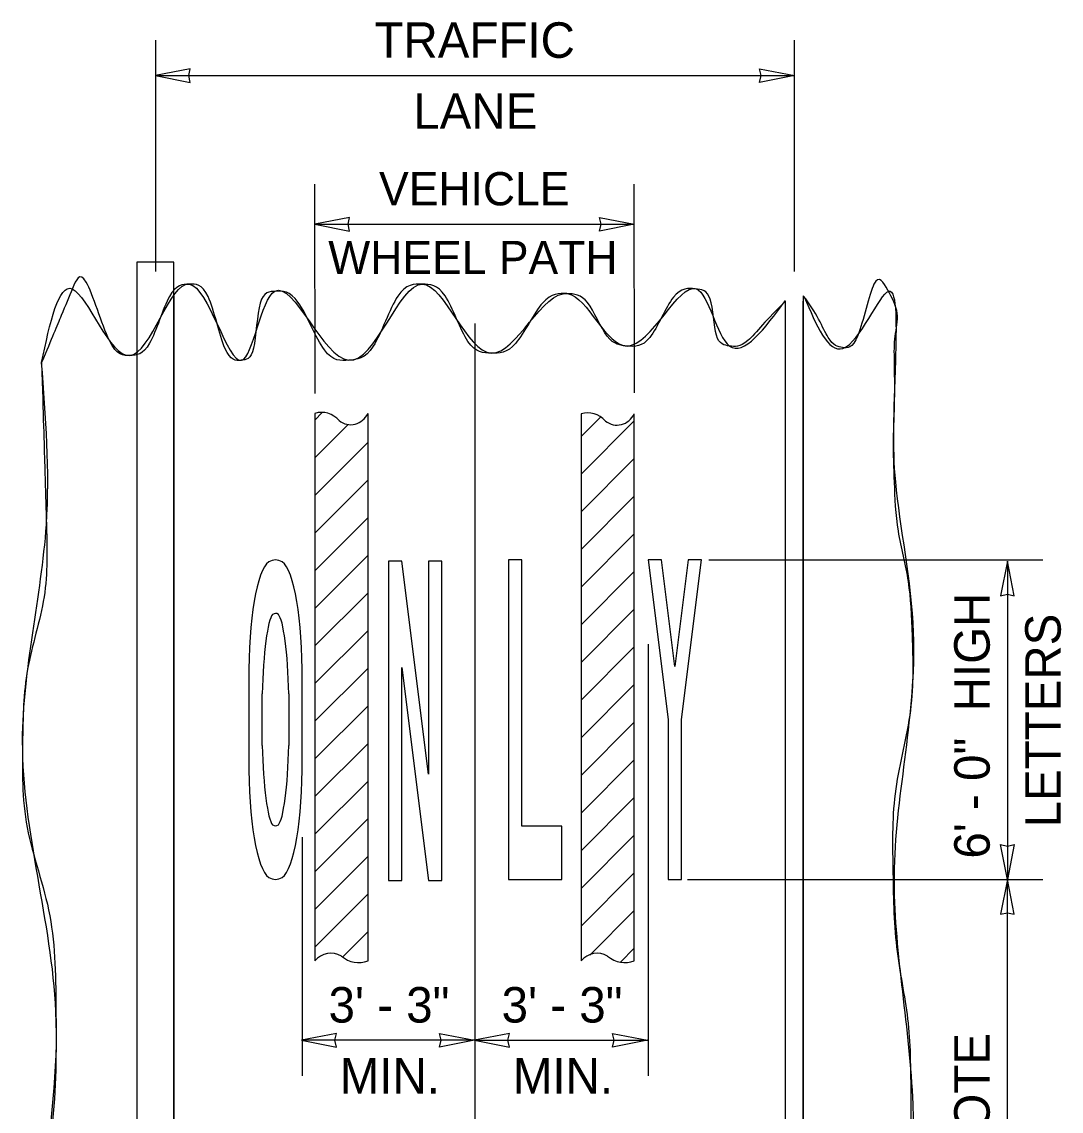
# Model space of a CAD drawing. Extents: x 99862 to 103151, y 100000 to 105076.
# Drawn here: x 100952.5 to 101421, y 103470.7 to 103961.7 of the extents above; entities that cross this region are included whole.
import ezdxf

# ---------------------------------------------------------------- set-up
doc = ezdxf.new("R2010")
doc.units = 0
for name, color, linetype in [('Level 15', 7, 'Continuous'), ('Level 2', 7, 'Continuous'), ('Level 20', 7, 'Continuous'), ('Level 3', 7, 'Continuous'), ('Level 6', 7, 'Continuous'), ('Level 8', 7, 'Continuous')]:
    doc.layers.add(name, color=color, linetype=linetype)

msp = doc.modelspace()

# ---------------------------------------------------------------- linework, layer by layer
at = {"layer": 'Level 15'}
for p, q in [((101012.75, 103953.45), (101012.75, 103849.09)), ((101300.75, 103849.09), (101300.75, 103953.45)), ((101012.75, 103937.45), (101300.75, 103937.45)), ((101084.7, 103794.19), (101084.57, 103888.45)), ((101228.7, 103794.47), (101228.57, 103888.45)), ((101084.57, 103870.45), (101228.57, 103870.45)), ((101156.75, 103825.76), (101156.75, 103449.32)), ((101262.12, 103719.16), (101412.75, 103719.16)), ((101396.75, 103718.66), (101396.75, 103575.16)), ((101234.87, 103681.16), (101234.87, 103486.65)), ((101078.87, 103594.16), (101078.87, 103486.65)), ((101252.62, 103575.16), (101412.75, 103575.16)), ((101396.75, 103330.16), (101396.75, 103575.16)), ((101156.54, 103502.65), (101078.59, 103502.65)), ((101156.6, 103502.65), (101234.5, 103502.65))]:
    msp.add_line(p, q, dxfattribs=at)
for points in [[(101012.75, 103937.45), (101028.47, 103934.37), (101027.74, 103937.45), (101028.47, 103940.54)], [(101300.75, 103937.45), (101285.02, 103934.37), (101285.75, 103937.45), (101285.02, 103940.54)], [(101084.57, 103870.45), (101100.29, 103867.37), (101099.56, 103870.45), (101100.29, 103873.54)], [(101228.57, 103870.45), (101212.84, 103867.37), (101213.57, 103870.45), (101212.84, 103873.54)], [(101396.75, 103718.66), (101393.66, 103702.93), (101396.75, 103703.66), (101399.83, 103702.93)], [(101396.75, 103575.16), (101393.66, 103590.88), (101396.75, 103590.15), (101399.83, 103590.88)], [(101396.75, 103575.16), (101393.66, 103559.43), (101396.75, 103560.16), (101399.83, 103559.43)], [(101078.59, 103502.65), (101094.32, 103499.56), (101093.59, 103502.65), (101094.32, 103505.73)], [(101156.54, 103502.65), (101140.82, 103499.56), (101141.54, 103502.65), (101140.82, 103505.73)], [(101156.6, 103502.65), (101172.32, 103499.56), (101171.6, 103502.65), (101172.32, 103505.73)], [(101234.5, 103502.65), (101218.77, 103499.56), (101219.5, 103502.65), (101218.77, 103505.73)]]:
    msp.add_lwpolyline(points, close=True, dxfattribs=at)
at = {"layer": 'Level 2'}
for p, q in [((101021.11, 103853.38), (101004.39, 103853.38)), ((101004.39, 103853.38), (101004.39, 103058.35)), ((101021.11, 103058.35), (101021.11, 103853.38))]:
    msp.add_line(p, q, dxfattribs=at)
msp.add_lwpolyline([(101004.39, 103058.35), (101021.11, 103058.35), (101021.11, 103853.38), (101004.39, 103853.38), (101004.39, 103058.35)], dxfattribs=at)
at = {"layer": 'Level 3'}
for points in [[(101304.75, 103838.15), (101304.75, 103082.21)], [(101296.75, 103090.4), (101296.75, 103835.74)]]:
    msp.add_lwpolyline(points, dxfattribs=at)
for points in [[(101296.75, 103835.74), (101288.25, 103827.86), (101278.48, 103814.55), (101271.46, 103815.57), (101264.59, 103816.56), (101263.94, 103840.6), (101256.44, 103841.31), (101246.29, 103842.27), (101235.48, 103814.7), (101225.34, 103815.57), (101216.37, 103816.33), (101207.55, 103838.82), (101198.52, 103839.16), (101187.52, 103839.58), (101174.74, 103812.21), (101164.2, 103812.35), (101153.55, 103812.48), (101143.34, 103843.23), (101133.09, 103843.45), (101121.95, 103843.69), (101110.94, 103810), (101099.84, 103809.13), (101089.26, 103808.3), (101076.74, 103840.64), (101066.59, 103840.24), (101058.89, 103839.93), (101057.79, 103809.6), (101051.57, 103809.13), (101044.07, 103808.57), (101036.77, 103843.74), (101027.97, 103843.45), (101019.13, 103843.16), (101010.13, 103811.64), (101001.16, 103811.27), (100992.66, 103810.93), (100980.35, 103853.51), (100975.28, 103841.31), (100970.68, 103830.22), (100966.07, 103819.14), (100961.47, 103808.06)], [(101304.75, 103082.21), (101308.34, 103076.47), (101311.83, 103070.52), (101315.23, 103075.34), (101322.05, 103074.98), (101328.22, 103095.02), (101334.54, 103095.55), (101340.58, 103096.06), (101346.64, 103064.75), (101350.63, 103074.81), (101357.29, 103086.58), (101356.08, 103103.39), (101355.45, 103120.22), (101353.4, 103175.64), (101342.81, 103231.02), (101342.58, 103286.48), (101342.32, 103351.14), (101353.76, 103416.02), (101353.31, 103480.63), (101353.09, 103512.28), (101345.78, 103543.91), (101345.26, 103580.55), (101344.69, 103615.94), (101355.09, 103651.35), (101353.85, 103686.74), (101353.04, 103709.53), (101346.67, 103732.08), (101345.8, 103754.86), (101345.11, 103773.02), (101346.11, 103791.33), (101345.8, 103809.56), (101345.62, 103819.98), (101348.5, 103830.35), (101342.85, 103840.67), (101336.88, 103851.56), (101329.23, 103813.86), (101322.2, 103814.92), (101316.41, 103815.8), (101310.61, 103831.03), (101304.75, 103838.15)], [(100961.47, 103808.06), (100962.19, 103783.74), (100962.9, 103759.43), (100963.62, 103735.12), (100964.58, 103702.4), (100953.34, 103670.01), (100952.89, 103637.51), (100952.34, 103598.5), (100967.62, 103559.7), (100967.91, 103515.59), (100968.29, 103463.12), (100955.14, 103410.43), (100955.57, 103357.91), (100955.88, 103320.36), (100966.89, 103282.82), (100965.76, 103245.29), (100965.1, 103223.27), (100958.79, 103201.43), (100958.79, 103179.32), (100958.79, 103173.24), (100958.79, 103167.16), (100958.79, 103161.09), (100958.79, 103140.71), (100958.79, 103120.33), (100958.79, 103104.95), (100958.79, 103092.6), (100971.75, 103077.48), (100979.71, 103069.38), (100988.36, 103060.55), (100996.76, 103099.99), (101005.99, 103099.95), (101015.7, 103099.9), (101026.39, 103069.56), (101036.02, 103069.91), (101043.26, 103070.18), (101049.73, 103094.14), (101056.94, 103094.05), (101064.47, 103093.95), (101072.14, 103070.41), (101080.53, 103070.45), (101089.55, 103070.49), (101099.42, 103093.21), (101108.42, 103092.97), (101117.01, 103092.75), (101125.58, 103070.79), (101134.16, 103070.45), (101142.56, 103070.11), (101150.98, 103092.76), (101159.37, 103092.44), (101166.71, 103092.16), (101171.78, 103071), (101178.68, 103070.45), (101186.85, 103069.79), (101197.25, 103093.17), (101205.49, 103092.44), (101212.65, 103091.8), (101217.58, 103069.96), (101224.8, 103069.38), (101233.59, 103068.66), (101244.49, 103093.1), (101253.23, 103092.44), (101260.74, 103091.87), (101267.08, 103069.86), (101274.68, 103069.38), (101281.66, 103068.93), (101289.49, 103084.69), (101296.75, 103090.4)]]:
    msp.add_open_spline(points, degree=3, dxfattribs=at)
for points in [[(100961.47, 103808.06), (100975.28, 103841.31), (101001.16, 103811.27), (101027.97, 103843.45), (101051.57, 103809.13), (101066.59, 103840.24), (101099.84, 103809.13), (101133.09, 103843.45), (101164.2, 103812.35), (101198.52, 103839.16), (101225.34, 103815.57), (101256.44, 103841.31), (101271.46, 103815.57), (101296.75, 103836.1)], [(101305.17, 103837.72), (101322.62, 103814.49), (101343.27, 103840.24), (101346.22, 103809.13), (101346.22, 103754.42), (101354.27, 103686.31), (101345.69, 103580.12), (101353.73, 103480.19), (101343, 103286.05), (101355.88, 103119.79), (101351.05, 103074.38), (101334.96, 103095.12), (101315.65, 103074.91), (101305.17, 103081.78)], [(101296.75, 103091.01), (101274.68, 103069.38), (101253.23, 103092.44), (101224.8, 103069.38), (101205.49, 103092.44), (101178.68, 103070.45), (101159.37, 103092.44), (101134.16, 103070.45), (101108.42, 103092.97), (101080.53, 103070.45), (101056.94, 103094.05), (101036.02, 103069.91), (101005.99, 103099.95), (100979.71, 103069.38), (100958.79, 103104.95), (100958.79, 103161.09), (100958.79, 103179.32), (100965.76, 103245.29), (100955.57, 103357.91), (100967.91, 103515.59), (100952.89, 103637.51), (100963.62, 103735.12), (100961.47, 103808.06)]]:
    msp.add_spline(points, degree=3, dxfattribs=at)
at = {"layer": 'Level 6'}
for p, q in [((101296.75, 103090.05), (101296.75, 103835.82)), ((101304.75, 103082.26), (101304.75, 103835.82)), ((101084.57, 103782.18), (101087.95, 103785.56)), ((101084.57, 103765.21), (101099.61, 103780.26)), ((101204.57, 103774.74), (101213.42, 103783.59)), ((101204.57, 103757.77), (101228.57, 103781.77)), ((101084.57, 103748.24), (101108.57, 103772.24)), ((101204.57, 103740.8), (101228.57, 103764.8)), ((101084.57, 103731.27), (101108.57, 103755.27)), ((101204.57, 103723.83), (101228.57, 103747.83)), ((101084.57, 103714.3), (101108.57, 103738.3)), ((101204.57, 103706.86), (101228.57, 103730.86)), ((101084.57, 103697.33), (101108.57, 103721.33)), ((101204.57, 103689.89), (101228.57, 103713.89)), ((101084.57, 103680.36), (101108.57, 103704.36)), ((101204.57, 103672.92), (101228.57, 103696.92)), ((101084.57, 103663.39), (101108.57, 103687.39)), ((101204.57, 103655.95), (101228.57, 103679.95)), ((101084.57, 103646.42), (101108.57, 103670.42)), ((101204.57, 103638.98), (101228.57, 103662.98)), ((101084.57, 103629.45), (101108.57, 103653.45)), ((101204.57, 103622.01), (101228.57, 103646.01)), ((101084.57, 103612.48), (101108.57, 103636.48)), ((101204.57, 103605.04), (101228.57, 103629.04)), ((101084.57, 103595.51), (101108.57, 103619.51)), ((101204.57, 103588.07), (101228.57, 103612.07)), ((101084.57, 103578.54), (101108.57, 103602.54)), ((101204.57, 103571.1), (101228.57, 103595.1)), ((101084.57, 103561.57), (101108.57, 103585.57)), ((101204.57, 103554.13), (101228.57, 103578.13)), ((101084.57, 103544.6), (101108.57, 103568.6)), ((101208.49, 103541.08), (101228.57, 103561.16)), ((101097.17, 103540.22), (101108.57, 103551.63)), ((101222.29, 103537.91), (101228.57, 103544.19))]:
    msp.add_line(p, q, dxfattribs=at)
for points in [[(101021.16, 103084.59), (101021.16, 103838.23)], [(101004.44, 103813.06), (101004.44, 103099.36)], [(101084.57, 103785.21), (101084.57, 103538.43)], [(101108.57, 103538.43), (101108.57, 103785.21)], [(101204.57, 103785.02), (101204.57, 103538.43)], [(101228.57, 103538.43), (101228.57, 103785.02)]]:
    msp.add_lwpolyline(points, dxfattribs=at)
for centre, major_axis, ratio, start_param, end_param in [((101087.57, 103773.59), (0, -12.07), 0.917809, 2.334921, 3.41576), ((101100.76, 103789.74), (0, -9.64), 0.917809, 5.65539, 7.364579), ((101207.57, 103773.41), (0, -12.06), 0.918519, 2.334921, 3.41576), ((101220.76, 103789.55), (0, -9.63), 0.918519, 5.65539, 7.364579), ((101091.9, 103530.8), (0, -11.05), 0.917809, 2.66324, 3.950242), ((101104.4, 103551.5), (0, -13.84), 0.917809, 5.61869, 6.617383), ((101211.9, 103530.81), (0, -11.04), 0.918519, 2.66324, 3.950242), ((101224.4, 103551.49), (0, -13.83), 0.918519, 5.61869, 6.617383)]:
    msp.add_ellipse(centre, major_axis=major_axis, ratio=ratio, start_param=start_param, end_param=end_param, dxfattribs=at)
at = {"layer": 'Level 8'}
for p, q in [((101123.87, 103718.66), (101117.87, 103718.66)), ((101117.87, 103718.66), (101117.87, 103574.66)), ((101135.87, 103622.66), (101123.87, 103718.66)), ((101141.87, 103718.66), (101135.87, 103718.66)), ((101135.87, 103718.66), (101135.87, 103622.66)), ((101141.87, 103574.66), (101141.87, 103718.66)), ((101177.87, 103719.16), (101171.87, 103719.16)), ((101171.87, 103719.16), (101171.87, 103575.16)), ((101177.87, 103599.16), (101177.87, 103719.16)), ((101123.87, 103670.66), (101135.87, 103574.66)), ((101123.87, 103574.66), (101123.87, 103670.66)), ((101054.88, 103664.79), (101054.88, 103647.16)), ((101060.88, 103647.16), (101060.88, 103658.79)), ((101072.87, 103658.79), (101072.87, 103647.16)), ((101054.88, 103647.16), (101054.88, 103629.54)), ((101060.88, 103635.54), (101060.88, 103647.16)), ((101072.87, 103647.16), (101072.87, 103635.54)), ((101195.87, 103599.16), (101177.87, 103599.16)), ((101195.87, 103575.16), (101195.87, 103599.16)), ((101117.87, 103574.66), (101123.87, 103574.66)), ((101135.87, 103574.66), (101141.87, 103574.66)), ((101171.87, 103575.16), (101177.12, 103575.16)), ((101177.12, 103575.16), (101177.87, 103575.16)), ((101177.87, 103575.16), (101195.87, 103575.16))]:
    msp.add_line(p, q, dxfattribs=at)
for points in [[(101123.87, 103574.66), (101123.87, 103670.66), (101135.87, 103574.66), (101141.87, 103574.66), (101141.87, 103718.66), (101135.87, 103718.66), (101135.87, 103622.66), (101123.87, 103718.66), (101117.87, 103718.66), (101117.87, 103574.66), (101123.87, 103574.66)], [(101123.87, 103574.66), (101123.87, 103670.66), (101135.87, 103574.66), (101141.87, 103574.66), (101141.87, 103718.66), (101135.87, 103718.66), (101135.87, 103622.66), (101123.87, 103718.66), (101117.87, 103718.66), (101117.87, 103574.66), (101123.87, 103574.66)], [(101195.87, 103599.16), (101177.87, 103599.16), (101177.87, 103719.16), (101171.87, 103719.16), (101171.87, 103575.16), (101177.12, 103575.16), (101177.87, 103575.16), (101195.87, 103575.16), (101195.87, 103599.16)], [(101195.87, 103599.16), (101177.87, 103599.16), (101177.87, 103719.16), (101171.87, 103719.16), (101171.87, 103575.16), (101177.12, 103575.16), (101177.87, 103575.16), (101195.87, 103575.16), (101195.87, 103599.16)], [(101249.87, 103575.16), (101249.87, 103647.16), (101258.87, 103719.16), (101252.87, 103719.16), (101246.87, 103671.16), (101240.87, 103719.16), (101234.87, 103719.16), (101243.87, 103647.16), (101243.87, 103575.16), (101249.87, 103575.16)], [(101234.87, 103719.16), (101243.87, 103647.16), (101243.87, 103575.16), (101249.87, 103575.16), (101249.87, 103647.16), (101258.87, 103719.16), (101252.87, 103719.16), (101246.87, 103671.16), (101240.87, 103719.16), (101234.87, 103719.16)], [(101054.88, 103664.79), (101054.88, 103647.16), (101054.88, 103629.54)], [(101054.88, 103664.79), (101054.88, 103647.16), (101054.88, 103629.54)], [(101078.87, 103629.54), (101078.87, 103647.16), (101078.87, 103664.79)], [(101060.88, 103635.54), (101060.88, 103647.16), (101060.88, 103658.79)], [(101060.88, 103635.54), (101060.88, 103647.16), (101060.88, 103658.79)], [(101072.87, 103658.79), (101072.87, 103647.16), (101072.87, 103635.54)], [(101072.87, 103658.79), (101072.87, 103647.16), (101072.87, 103635.54)]]:
    msp.add_lwpolyline(points, dxfattribs=at)
msp.add_lwpolyline([(101249.87, 103647.16), (101258.87, 103719.16), (101252.87, 103719.16), (101246.87, 103671.16), (101240.87, 103719.16), (101234.87, 103719.16), (101243.87, 103647.16), (101243.87, 103575.16), (101249.87, 103575.16)], close=True, dxfattribs=at)
for centre, major_axis, ratio, start_param, end_param in [((101066.87, 103659.04), (1.5, -59.75), 0.19927, 3.270148, 4.611013), ((101066.87, 103659.04), (1.5, -59.75), 0.19927, 3.270148, 4.611013), ((101063.87, 103592.93), (-3.14, -126.23), 0.19927, 3.02647, 3.266464), ((101063.87, 103592.93), (-3.14, -126.23), 0.19927, 3.02647, 3.266464), ((101066.88, 103659.07), (-1.49, -59.72), 0.19927, 1.671693, 3.012646), ((101066.88, 103659.07), (-1.49, -59.72), 0.19927, 1.671693, 3.012646), ((101065.28, 103658.69), (-0.84, -36.1), 0.122012, 3.268533, 4.71248), ((101065.28, 103658.69), (-0.84, -36.1), 0.122012, 3.268533, 4.71248), ((101064.49, 103590.93), (-2.44, -104.14), 0.122012, 3.042541, 3.248082), ((101064.49, 103590.93), (-2.44, -104.14), 0.122012, 3.042541, 3.248082), ((101068.47, 103658.69), (0.84, -36.1), 0.122012, 1.570705, 3.018849), ((101068.47, 103658.69), (0.84, -36.1), 0.122012, 1.570705, 3.018849), ((101065.28, 103635.64), (0.84, -36.1), 0.122012, 4.712298, 6.156245), ((101065.28, 103635.64), (0.84, -36.1), 0.122012, 4.712298, 6.156245), ((101068.47, 103635.64), (-0.84, -36.1), 0.122012, 0.122744, 1.570888), ((101068.47, 103635.64), (-0.84, -36.1), 0.122012, 0.122744, 1.570888), ((101066.87, 103635.29), (-1.5, -59.75), 0.19927, 4.813765, 6.15463), ((101066.87, 103635.29), (-1.5, -59.75), 0.19927, 4.813765, 6.15463), ((101066.88, 103635.26), (1.49, -59.72), 0.19927, 0.128946, 1.4699), ((101066.88, 103635.26), (1.49, -59.72), 0.19927, 0.128946, 1.4699), ((101064.49, 103703.4), (2.44, -104.14), 0.122012, 6.176696, 6.382237), ((101064.49, 103703.4), (2.44, -104.14), 0.122012, 6.176696, 6.382237), ((101063.87, 103701.4), (3.14, -126.23), 0.19927, 6.158314, 6.398307), ((101063.87, 103701.4), (3.14, -126.23), 0.19927, 6.158314, 6.398307)]:
    msp.add_ellipse(centre, major_axis=major_axis, ratio=ratio, start_param=start_param, end_param=end_param, dxfattribs=at)

# ---------------------------------------------------------------- texts
at = {"layer": 'Level 20'}
for s, height, rotation, p in [('TRAFFIC', 16, 360, (101111.48, 103945.45)), ('LANE', 16, 360, (101128.97, 103913.45)), ('VEHICLE', 15, 360, (101113.54, 103878.95)), ('WHEEL PATH', 15, 360, (101090.63, 103847.95)), ('6\' - 0"  HIGH', 16, 90, (101388.75, 103584.54)), ('LETTERS', 16, 90, (101420.75, 103598.61)), ('3\' - 3"', 16, 360, (101090.78, 103510.65)), ('3\' - 3"', 16, 360, (101168.78, 103510.65)), ('SEE NOTE', 16, 90, (101388.75, 103397.72)), ('MIN.', 16, 360, (101095.84, 103478.65)), ('MIN.', 16, 360, (101173.84, 103478.65))]:
    msp.add_text(s, height=height, rotation=rotation, dxfattribs=at).set_placement(p)

doc.saveas('drawing.dxf')
